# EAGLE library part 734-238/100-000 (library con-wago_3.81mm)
Serie 734, Stiftleiste (für Leiterplatten) Einpressstift 0,6 x 0,6 mm / Series 734, Male header (for PCBs) Press-in pin 0.6 x 0.6 mm Polzahl / Pole No.: 8 Rastermaß / Pitch: 3.81 mm Bemessungsspannung / Rated Voltage: 160 V Nennstrom / Nominal Current: 8 A Farbe / Color: orange / orange Stand: 01.01.2012. Die jeweils aktuellen Daten zu diesem Artikel finden Sie in unserem Produktkatalog, den Sie unter www.wago.com einsehen können. As of: 01/01/2012. Please find the newest data for this article in our product catalogue, which can be viewed under www.wago.com.
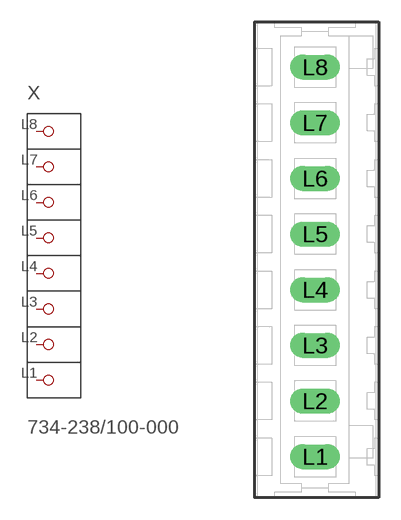
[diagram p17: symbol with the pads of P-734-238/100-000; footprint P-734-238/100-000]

Designator prefix X

## 734-238/100-000  [P-734-238/100-000]
L1  P1
L2  P2
L3  P3
L4  P4
L5  P5
L6  P6
L7  P7
L8  P8

## Footprint P-734-238/100-000 (pad centres in mm)
drill 1.15 long: L1 -0.1,-13.485; L2 -0.1,-9.675; L3 -0.1,-5.865; L4 -0.1,-2.055; L5 -0.1,1.755; L6 -0.1,5.565; L7 -0.1,9.375; L8 -0.1,13.185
